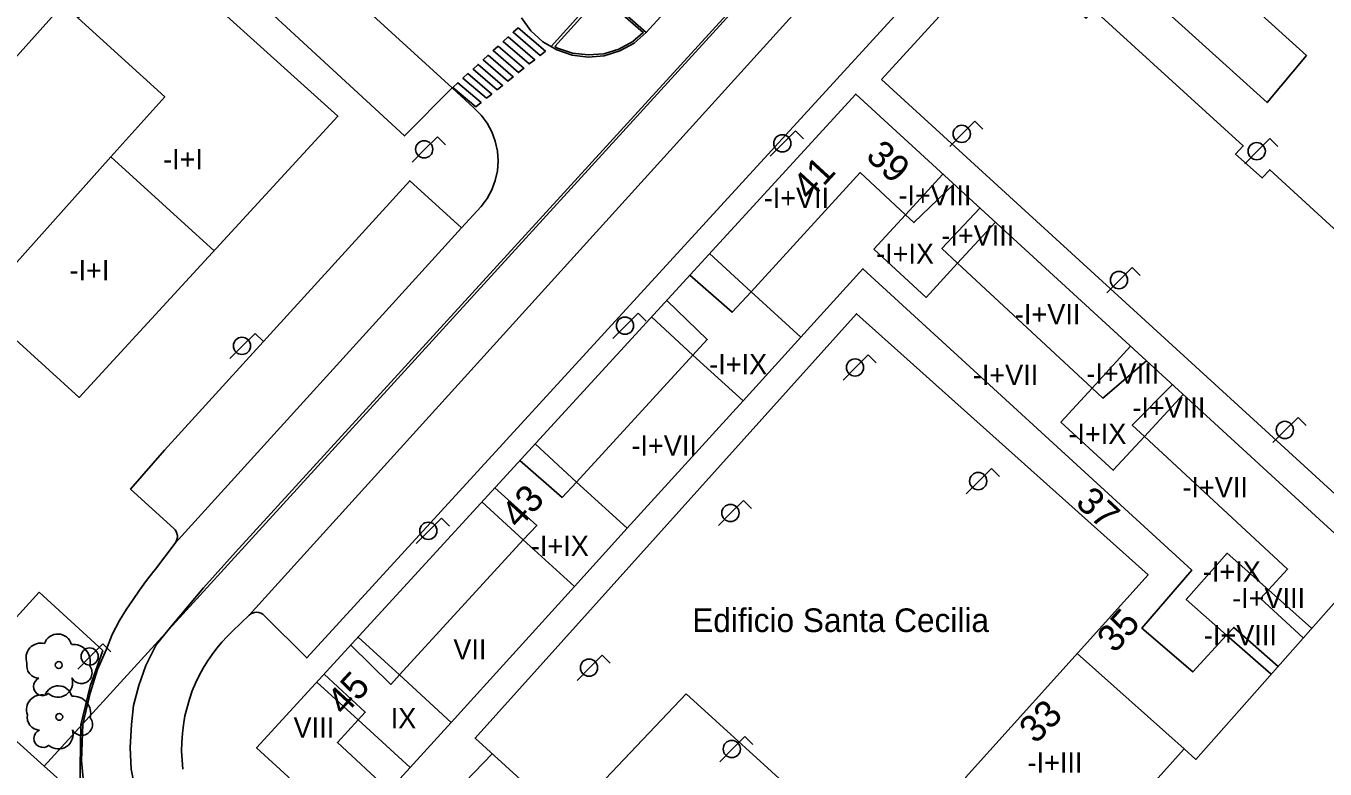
# Model space of a CAD drawing. Extents: x 282771 to 285132, y 4823109 to 4825496.
# Drawn here: x 283795 to 283891.2, y 4823192.6 to 4823247.6 of the extents above; entities that cross this region are included whole.
import ezdxf

# ---------------------------------------------------------------- set-up
doc = ezdxf.new("R2010")
doc.units = 0
for name, color, linetype in [('ACERA-BORDILLO', 7, 'Continuous'), ('ACERA-INTERIOR', 7, 'Continuous'), ('ARBOL', 7, 'Continuous'), ('BORDILLO', 7, 'Continuous'), ('CALLE-EJE', 7, 'Continuous'), ('EDIFICIO', 7, 'Continuous'), ('FAROLA', 7, 'Continuous'), ('MEDIANERA', 7, 'Continuous'), ('NUM-PORTAL', 7, 'Continuous'), ('PASO-PEATONES', 7, 'Continuous'), ('SENAL-VIARIA', 7, 'Continuous'), ('TXT-ALTURA-EDIFICIO', 7, 'Continuous'), ('TXT-EDIFICIOS', 7, 'Continuous'), ('ZONA-VERDE', 7, 'Continuous')]:
    doc.layers.add(name, color=color, linetype=linetype)

msp = doc.modelspace()

# ---------------------------------------------------------------- linework, layer by layer
at = {"layer": 'ACERA-BORDILLO'}
for points in [[(283806.591, 4823192.62), (283806.527, 4823193.276), (283806.499, 4823193.935), (283806.508, 4823194.594), (283806.552, 4823195.251), (283806.633, 4823195.903), (283806.748, 4823196.547), (283806.897, 4823197.179), (283807.079, 4823197.798), (283807.291, 4823198.401), (283807.533, 4823198.986), (283807.802, 4823199.55), (283808.096, 4823200.093), (283808.413, 4823200.613), (283808.751, 4823201.109), (283809.107, 4823201.58), (283809.478, 4823202.025), (283809.864, 4823202.444), (283810.261, 4823202.836), (283811.505, 4823204.011), (283811.618, 4823204.1), (283811.753, 4823204.17), (283811.905, 4823204.215), (283812.066, 4823204.229), (283812.226, 4823204.21), (283812.376, 4823204.161), (283812.509, 4823204.087), (283812.62, 4823203.995), (283815.762, 4823200.853), (283909.081, 4823302.722)], [(283785.182, 4823274.332), (283823.002, 4823239.502), (283826.552, 4823243.052), (283828.161, 4823241.552)], [(283828.161, 4823241.552), (283828.681, 4823241.032), (283829.121, 4823240.442), (283829.471, 4823239.792), (283829.731, 4823239.102), (283829.891, 4823238.382), (283829.941, 4823237.652), (283829.891, 4823236.922), (283829.731, 4823236.202), (283829.471, 4823235.512), (283829.121, 4823234.862), (283828.681, 4823234.282), (283827.222, 4823232.702), (283823.392, 4823236.182), (283805.242, 4823216.233), (283802.712, 4823213.333), (283805.924, 4823210.426), (283806.019, 4823210.324), (283806.098, 4823210.2), (283806.154, 4823210.06), (283806.184, 4823209.908), (283806.183, 4823209.753), (283806.154, 4823209.604), (283806.1, 4823209.469), (283806.026, 4823209.351), (283804.572, 4823207.423), (283804.447, 4823207.274), (283803.896, 4823206.587), (283803.367, 4823205.863), (283802.863, 4823205.103), (283802.406, 4823204.446), (283801.907, 4823203.61), (283801.35, 4823202.583), (283800.939, 4823201.497), (283800.279, 4823200.001), (283799.724, 4823198.246), (283799.185, 4823195.935), (283799.083, 4823193.239), (283799.288, 4823191.108)]]:
    msp.add_lwpolyline(points, dxfattribs=at)
at = {"layer": 'ACERA-INTERIOR'}
msp.add_lwpolyline([(283837.494, 4823250.169), (283833.866, 4823246.114)], dxfattribs=at)
at = {"layer": 'ARBOL'}
for centre in [(283797.398, 4823200.318), (283797.432, 4823196.483)]:
    msp.add_circle(centre, 0.255, dxfattribs=at)
for centre, radius, start, end in [((283797.328, 4823201.578), 1.038, 15.64228, 161.38435), ((283796.068, 4823200.848), 1.097, 75.4318, 200.55608), ((283798.458, 4823200.578), 1.272, 345.03273, 95.79925), ((283795.958, 4823200.278), 0.935, 168.59898, 268.13236), ((283799.068, 4823199.748), 0.797, 208.96246, 38.99103), ((283796.198, 4823198.728), 0.672, 113.73672, 309.4725), ((283797.338, 4823199.028), 1.086, 228.95447, 17.92796), ((283797.362, 4823197.743), 1.038, 15.64228, 161.38435), ((283796.102, 4823197.013), 1.097, 75.4318, 200.55608), ((283798.492, 4823196.743), 1.272, 345.03273, 95.79925), ((283795.992, 4823196.443), 0.935, 168.59898, 268.13236), ((283799.102, 4823195.913), 0.797, 208.96246, 38.99103), ((283796.232, 4823194.893), 0.672, 113.73672, 309.4725), ((283797.372, 4823195.193), 1.086, 228.95447, 17.92796)]:
    msp.add_arc(centre, radius, start, end, dxfattribs=at)
at = {"layer": 'BORDILLO'}
msp.add_lwpolyline([(283831.671, 4823248.252), (283832.371, 4823247.282), (283833.261, 4823246.472), (283834.291, 4823245.862), (283835.431, 4823245.482), (283836.621, 4823245.342), (283837.811, 4823245.442), (283838.951, 4823245.792), (283840.011, 4823246.372), (283840.921, 4823247.152), (283837.494, 4823250.169)], dxfattribs=at)
at = {"layer": 'CALLE-EJE'}
for points in [[(283796.312, 4823192.833), (283855.611, 4823257.812), (283918.081, 4823326.402)], [(283707.963, 4823272.552), (283796.312, 4823192.833)], [(283796.312, 4823192.833), (283890.208, 4823109)]]:
    msp.add_lwpolyline(points, dxfattribs=at)
at = {"layer": 'EDIFICIO'}
for points in [[(283796.432, 4823260.512), (283791.402, 4823254.952), (283798.842, 4823248.222), (283803.872, 4823253.782), (283818.072, 4823240.962), (283798.912, 4823220.132), (283791.392, 4823226.942), (283788.452, 4823223.742), (283780.992, 4823230.602), (283777.722, 4823233.612), (283775.052, 4823236.092), (283771.402, 4823231.842), (283758.302, 4823243.812), (283783.892, 4823271.862), (283796.432, 4823260.512)], [(283867.771, 4823188.923), (283864.572, 4823191.991), (283878.091, 4823206.993), (283856.501, 4823226.332), (283828.232, 4823194.913), (283858.021, 4823167.753), (283850.051, 4823159.423), (283829.922, 4823177.833), (283812.052, 4823194.193), (283856.441, 4823242.592), (283891.081, 4823210.833), (283894.411, 4823207.783), (283891.081, 4823204.023), (283881.621, 4823193.333), (283880.771, 4823194.103), (283873.241, 4823185.723), (283870.611, 4823188.113), (283866.461, 4823183.193), (283864.501, 4823185.023), (283867.771, 4823188.923)]]:
    msp.add_lwpolyline(points, dxfattribs=at)
at = {"layer": 'FAROLA'}
for p, q in [((283851.979, 4823239.877), (283851.039, 4823238.947)), ((283852.568, 4823239.287), (283851.979, 4823239.877)), ((283865.271, 4823240.58), (283864.331, 4823239.65)), ((283865.861, 4823239.99), (283865.271, 4823240.58)), ((283825.451, 4823239.438), (283824.511, 4823238.508)), ((283826.041, 4823238.848), (283825.451, 4823239.438)), ((283851.039, 4823238.947), (283850.109, 4823238.007)), ((283864.331, 4823239.65), (283863.401, 4823238.71)), ((283887.121, 4823239.299), (283886.181, 4823238.369)), ((283887.711, 4823238.709), (283887.121, 4823239.299)), ((283824.511, 4823238.508), (283823.581, 4823237.568)), ((283886.181, 4823238.369), (283885.251, 4823237.429)), ((283876.916, 4823229.755), (283875.976, 4823228.825)), ((283877.506, 4823229.165), (283876.916, 4823229.755)), ((283875.976, 4823228.825), (283875.046, 4823227.885)), ((283840.322, 4823226.377), (283839.382, 4823225.447)), ((283840.912, 4823225.787), (283840.322, 4823226.377)), ((283839.382, 4823225.447), (283838.452, 4823224.507)), ((283811.947, 4823224.881), (283811.007, 4823223.951)), ((283812.537, 4823224.291), (283811.947, 4823224.881)), ((283811.007, 4823223.951), (283810.077, 4823223.011)), ((283857.363, 4823223.28), (283856.423, 4823222.35)), ((283857.953, 4823222.69), (283857.363, 4823223.28)), ((283856.423, 4823222.35), (283855.493, 4823221.41)), ((283889.205, 4823218.658), (283888.265, 4823217.728)), ((283889.795, 4823218.068), (283889.205, 4823218.658)), ((283888.265, 4823217.728), (283887.335, 4823216.788)), ((283866.49, 4823214.871), (283865.55, 4823213.941)), ((283867.08, 4823214.281), (283866.49, 4823214.871)), ((283865.55, 4823213.941), (283864.62, 4823213.001)), ((283848.133, 4823212.512), (283847.193, 4823211.582)), ((283848.723, 4823211.922), (283848.133, 4823212.512)), ((283825.752, 4823211.192), (283824.812, 4823210.262)), ((283826.342, 4823210.602), (283825.752, 4823211.192)), ((283847.193, 4823211.582), (283846.263, 4823210.642)), ((283824.812, 4823210.262), (283823.882, 4823209.322)), ((283800.668, 4823201.882), (283799.728, 4823200.952)), ((283801.258, 4823201.292), (283800.668, 4823201.882)), ((283799.728, 4823200.952), (283798.798, 4823200.012)), ((283837.661, 4823201.053), (283836.721, 4823200.123)), ((283838.251, 4823200.463), (283837.661, 4823201.053)), ((283836.721, 4823200.123), (283835.791, 4823199.183)), ((283848.232, 4823195.03), (283847.292, 4823194.1)), ((283848.822, 4823194.44), (283848.232, 4823195.03)), ((283847.292, 4823194.1), (283846.362, 4823193.16))]:
    msp.add_line(p, q, dxfattribs=at)
for centre, radius in [((283864.291, 4823239.65), 0.638), ((283824.471, 4823238.508), 0.637), ((283850.999, 4823238.947), 0.637), ((283886.141, 4823238.369), 0.638), ((283875.936, 4823228.825), 0.638), ((283839.342, 4823225.447), 0.637), ((283810.967, 4823223.951), 0.637), ((283856.383, 4823222.35), 0.637), ((283888.225, 4823217.728), 0.638), ((283865.51, 4823213.941), 0.637), ((283847.153, 4823211.582), 0.637), ((283824.772, 4823210.262), 0.637), ((283799.688, 4823200.952), 0.637), ((283836.681, 4823200.123), 0.637), ((283847.252, 4823194.1), 0.637)]:
    msp.add_circle(centre, radius, dxfattribs=at)
at = {"layer": 'MEDIANERA'}
for points in [[(283797.729, 4823249.229), (283793.892, 4823244.962), (283784.972, 4823235.042)], [(283801.252, 4823237.942), (283805.252, 4823242.402), (283798.842, 4823248.222)], [(283791.392, 4823226.942), (283801.252, 4823237.942)], [(283801.252, 4823237.942), (283808.912, 4823231.002)], [(283860.121, 4823233.662), (283856.771, 4823236.782), (283848.681, 4823227.952)], [(283860.121, 4823233.662), (283862.881, 4823236.662)], [(283860.121, 4823233.662), (283860.751, 4823233.082), (283863.701, 4823235.922)], [(283863.981, 4823230.072), (283862.821, 4823231.162), (283865.641, 4823234.142)], [(283863.981, 4823230.072), (283861.651, 4823227.542), (283857.781, 4823231.112), (283860.121, 4823233.662)], [(283863.981, 4823230.072), (283866.771, 4823233.092)], [(283848.681, 4823227.952), (283845.601, 4823230.782)], [(283873.951, 4823220.823), (283863.981, 4823230.072)], [(283848.681, 4823227.952), (283847.291, 4823226.442), (283844.141, 4823229.182)], [(283883.911, 4823202.533), (283881.401, 4823199.813), (283877.631, 4823203.053), (283881.331, 4823207.343), (283856.971, 4823229.662), (283852.361, 4823224.592)], [(283842.431, 4823227.322), (283845.441, 4823224.432), (283844.371, 4823223.272)], [(283848.681, 4823227.952), (283852.361, 4823224.592)], [(283844.371, 4823223.272), (283841.301, 4823226.092)], [(283852.361, 4823224.592), (283848.091, 4823219.883)], [(283873.951, 4823220.823), (283876.791, 4823223.922)], [(283835.751, 4823213.873), (283844.371, 4823223.272)], [(283844.371, 4823223.272), (283848.091, 4823219.883)], [(283873.951, 4823220.823), (283874.751, 4823220.093), (283877.971, 4823222.852)], [(283877.821, 4823217.243), (283875.511, 4823214.743), (283871.641, 4823218.313), (283873.951, 4823220.823)], [(283877.821, 4823217.243), (283876.921, 4823218.083), (283879.891, 4823221.093)], [(283848.091, 4823219.883), (283839.511, 4823210.443)], [(283877.821, 4823217.243), (283880.691, 4823220.353)], [(283835.751, 4823213.873), (283832.681, 4823216.693)], [(283887.001, 4823205.883), (283888.431, 4823207.423), (283877.821, 4823217.243)], [(283835.751, 4823213.873), (283834.701, 4823212.733), (283831.551, 4823215.453)], [(283839.511, 4823210.443), (283835.751, 4823213.873)], [(283829.701, 4823213.443), (283832.801, 4823210.663), (283831.811, 4823209.583)], [(283831.811, 4823209.583), (283828.742, 4823212.403)], [(283835.591, 4823206.133), (283839.511, 4823210.443)], [(283822.632, 4823199.583), (283831.811, 4823209.583)], [(283831.811, 4823209.583), (283835.591, 4823206.133)], [(283883.911, 4823202.533), (283880.921, 4823205.183), (283883.961, 4823208.593), (283887.001, 4823205.883)], [(283826.472, 4823196.073), (283835.591, 4823206.133)], [(283889.591, 4823202.343), (283886.421, 4823205.253), (283887.001, 4823205.883)], [(283887.001, 4823205.883), (283890.211, 4823203.043)], [(283822.632, 4823199.583), (283819.572, 4823202.393)], [(283883.911, 4823202.533), (283884.441, 4823203.103), (283887.721, 4823200.223)], [(283887.201, 4823199.643), (283883.911, 4823202.533)], [(283819.022, 4823201.793), (283821.992, 4823198.883), (283822.632, 4823199.583)], [(283872.851, 4823201.173), (283880.771, 4823194.103)], [(283817.052, 4823199.653), (283820.102, 4823196.823), (283819.582, 4823196.253)], [(283822.632, 4823199.583), (283826.472, 4823196.073)], [(283819.582, 4823196.253), (283816.512, 4823199.063)], [(283823.422, 4823192.743), (283821.882, 4823191.033), (283818.042, 4823194.573), (283819.582, 4823196.253)], [(283819.582, 4823196.253), (283823.422, 4823192.743)], [(283823.422, 4823192.743), (283826.472, 4823196.073)], [(283829.492, 4823193.753), (283821.552, 4823185.493)]]:
    msp.add_lwpolyline(points, dxfattribs=at)
at = {"layer": 'PASO-PEATONES'}
for points in [[(283831.43, 4823247.513), (283833.448, 4823245.78), (283833.051, 4823245.462), (283831.058, 4823247.173)], [(283830.686, 4823246.833), (283832.653, 4823245.144), (283832.256, 4823244.827), (283830.315, 4823246.493)], [(283829.2, 4823245.474), (283831.064, 4823243.873), (283830.666, 4823243.555), (283828.828, 4823245.134)], [(283829.943, 4823246.153), (283831.859, 4823244.509), (283831.461, 4823244.191), (283829.571, 4823245.814)], [(283829.872, 4823242.92), (283828.084, 4823244.454), (283828.456, 4823244.794), (283830.269, 4823243.238)], [(283829.077, 4823242.284), (283827.341, 4823243.774), (283827.713, 4823244.114), (283829.474, 4823242.602)], [(283828.282, 4823241.648), (283826.598, 4823243.094), (283826.969, 4823243.434), (283828.679, 4823241.966)]]:
    msp.add_lwpolyline(points, close=True, dxfattribs=at)
at = {"layer": 'SENAL-VIARIA'}
for points in [[(283811.505, 4823204.011), (283904.606, 4823306.733)], [(283899.191, 4823305.74), (283810.501, 4823208.666)], [(283869.051, 4823277.932), (283840.921, 4823247.152)], [(283792.672, 4823273.932), (283826.552, 4823243.052)], [(283806.026, 4823209.351), (283827.222, 4823232.702)], [(283810.501, 4823208.666), (283808.123, 4823206.046), (283805.787, 4823203.26), (283804.619, 4823201.822), (283803.856, 4823200.294), (283803.319, 4823198.795), (283802.937, 4823197.328), (283802.776, 4823195.905), (283802.688, 4823194.217), (283802.761, 4823192.618), (283803.047, 4823191.099), (283803.605, 4823189.353), (283804.294, 4823187.607), (283805.247, 4823186.155), (283806.083, 4823185.172)]]:
    msp.add_lwpolyline(points, dxfattribs=at)
at = {"layer": 'ZONA-VERDE'}
for p, q in [((283868.09, 4823254.338), (283858.346, 4823243.676)), ((283837.562, 4823249.909), (283834.157, 4823246.116)), ((283858.346, 4823243.676), (283895.108, 4823210.08)), ((283784.075, 4823192.746), (283795.943, 4823205.705)), ((283795.943, 4823205.705), (283800.651, 4823201.391)), ((283800.651, 4823201.391), (283799.713, 4823198.764)), ((283799.713, 4823198.764), (283799.023, 4823195.903)), ((283835.427, 4823189.308), (283843.867, 4823198.178)), ((283843.867, 4823198.178), (283864.717, 4823179.278)), ((283799.023, 4823195.903), (283798.961, 4823191.179))]:
    msp.add_line(p, q, dxfattribs=at)
for points in [[(283904.852, 4823220.741), (283887.11, 4823236.992), (283886.555, 4823236.393), (283884.57, 4823238.147), (283885.143, 4823238.765), (283874.083, 4823248.846), (283873.512, 4823248.231), (283871.222, 4823250.279), (283871.824, 4823250.94), (283868.09, 4823254.338)], [(283889.836, 4823245.463), (283881.636, 4823252.891), (283878.577, 4823249.494), (283886.903, 4823241.964), (283889.836, 4823245.463)], [(283834.157, 4823246.116), (283834.354, 4823245.999), (283835.464, 4823245.629), (283836.624, 4823245.493), (283837.783, 4823245.59), (283838.893, 4823245.931), (283839.926, 4823246.496), (283840.693, 4823247.154), (283837.562, 4823249.909)]]:
    msp.add_lwpolyline(points, dxfattribs=at)

# ---------------------------------------------------------------- texts
at = {"layer": 'NUM-PORTAL'}
for s, rotation, p in [('39', 317.26004, (283857.094, 4823237.894)), ('41', 47.33004, (283853.038, 4823234.62)), ('43', 47.33004, (283831.46, 4823210.328)), ('37', 317.26004, (283872.627, 4823212.232)), ('35', 48.50353, (283875.631, 4823201.129)), ('45', 47.33004, (283818.539, 4823196.481)), ('33', 44.65532, (283869.755, 4823194.419))]:
    msp.add_text(s, height=2, rotation=rotation, dxfattribs=at).set_placement(p)
at = {"layer": 'TXT-ALTURA-EDIFICIO'}
for s, p in [('-I+I', (283805.128, 4823237.032)), ('-I+VIII', (283859.598, 4823234.352)), ('-I+VII', (283849.619, 4823234.162)), ('-I+VIII', (283862.778, 4823231.382)), ('-I+IX', (283857.942, 4823230.032)), ('-I+I', (283798.191, 4823228.804)), ('-I+VII', (283868.229, 4823225.552)), ('-I+IX', (283845.582, 4823221.852)), ('-I+VII', (283865.109, 4823221.052)), ('-I+VIII', (283873.518, 4823221.162)), ('-I+VIII', (283876.928, 4823218.633)), ('-I+IX', (283872.192, 4823216.693)), ('-I+VII', (283839.819, 4823215.823)), ('-I+VII', (283880.639, 4823212.733)), ('-I+IX', (283832.372, 4823208.393)), ('-I+IX', (283882.152, 4823206.493)), ('-I+VIII', (283884.318, 4823204.533)), ('-I+VIII', (283882.228, 4823201.783)), ('VII', (283826.631, 4823200.733)), ('VIII', (283814.791, 4823194.953)), ('IX', (283821.985, 4823195.633)), ('-I+III', (283869.167, 4823192.353))]:
    msp.add_text(s, height=1.5, rotation=0.00004, dxfattribs=at).set_placement(p)
at = {"layer": 'TXT-EDIFICIOS'}
msp.add_text('Edificio Santa Cecilia', height=1.75, rotation=0.00004, dxfattribs=at).set_placement((283844.325, 4823202.763))

doc.saveas('drawing.dxf')
